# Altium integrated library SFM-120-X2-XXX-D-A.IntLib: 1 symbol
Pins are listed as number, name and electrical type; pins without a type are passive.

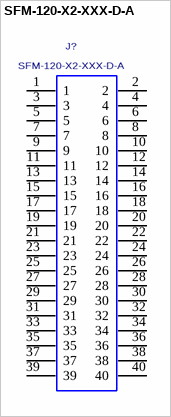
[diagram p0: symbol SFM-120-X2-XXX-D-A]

## SFM-120-X2-XXX-D-A
designator J?
SOCKET STRIP, .050" (1.27mm) PITCH, SURFACE MOUNT.; MANUFACTURER: SAMTEC
footprint SFM-120-X2-XXX-D-A
pins: 1, 2, 3, 4, 5, 6, 7, 8, 9, 10, 11, 12, 13, 14, 15, 16, 17, 18, 19, 20, 21, 22, 23, 24, 25, 26, 27, 28, 29, 30, 31, 32, 33, 34, 35, 36, 37, 38, 39, 40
